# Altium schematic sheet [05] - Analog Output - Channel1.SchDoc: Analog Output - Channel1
size A2; DrawnBy: Ankur Dubey; DocumentNumber: 5; SheetNumber: 5; SheetTotal: 16
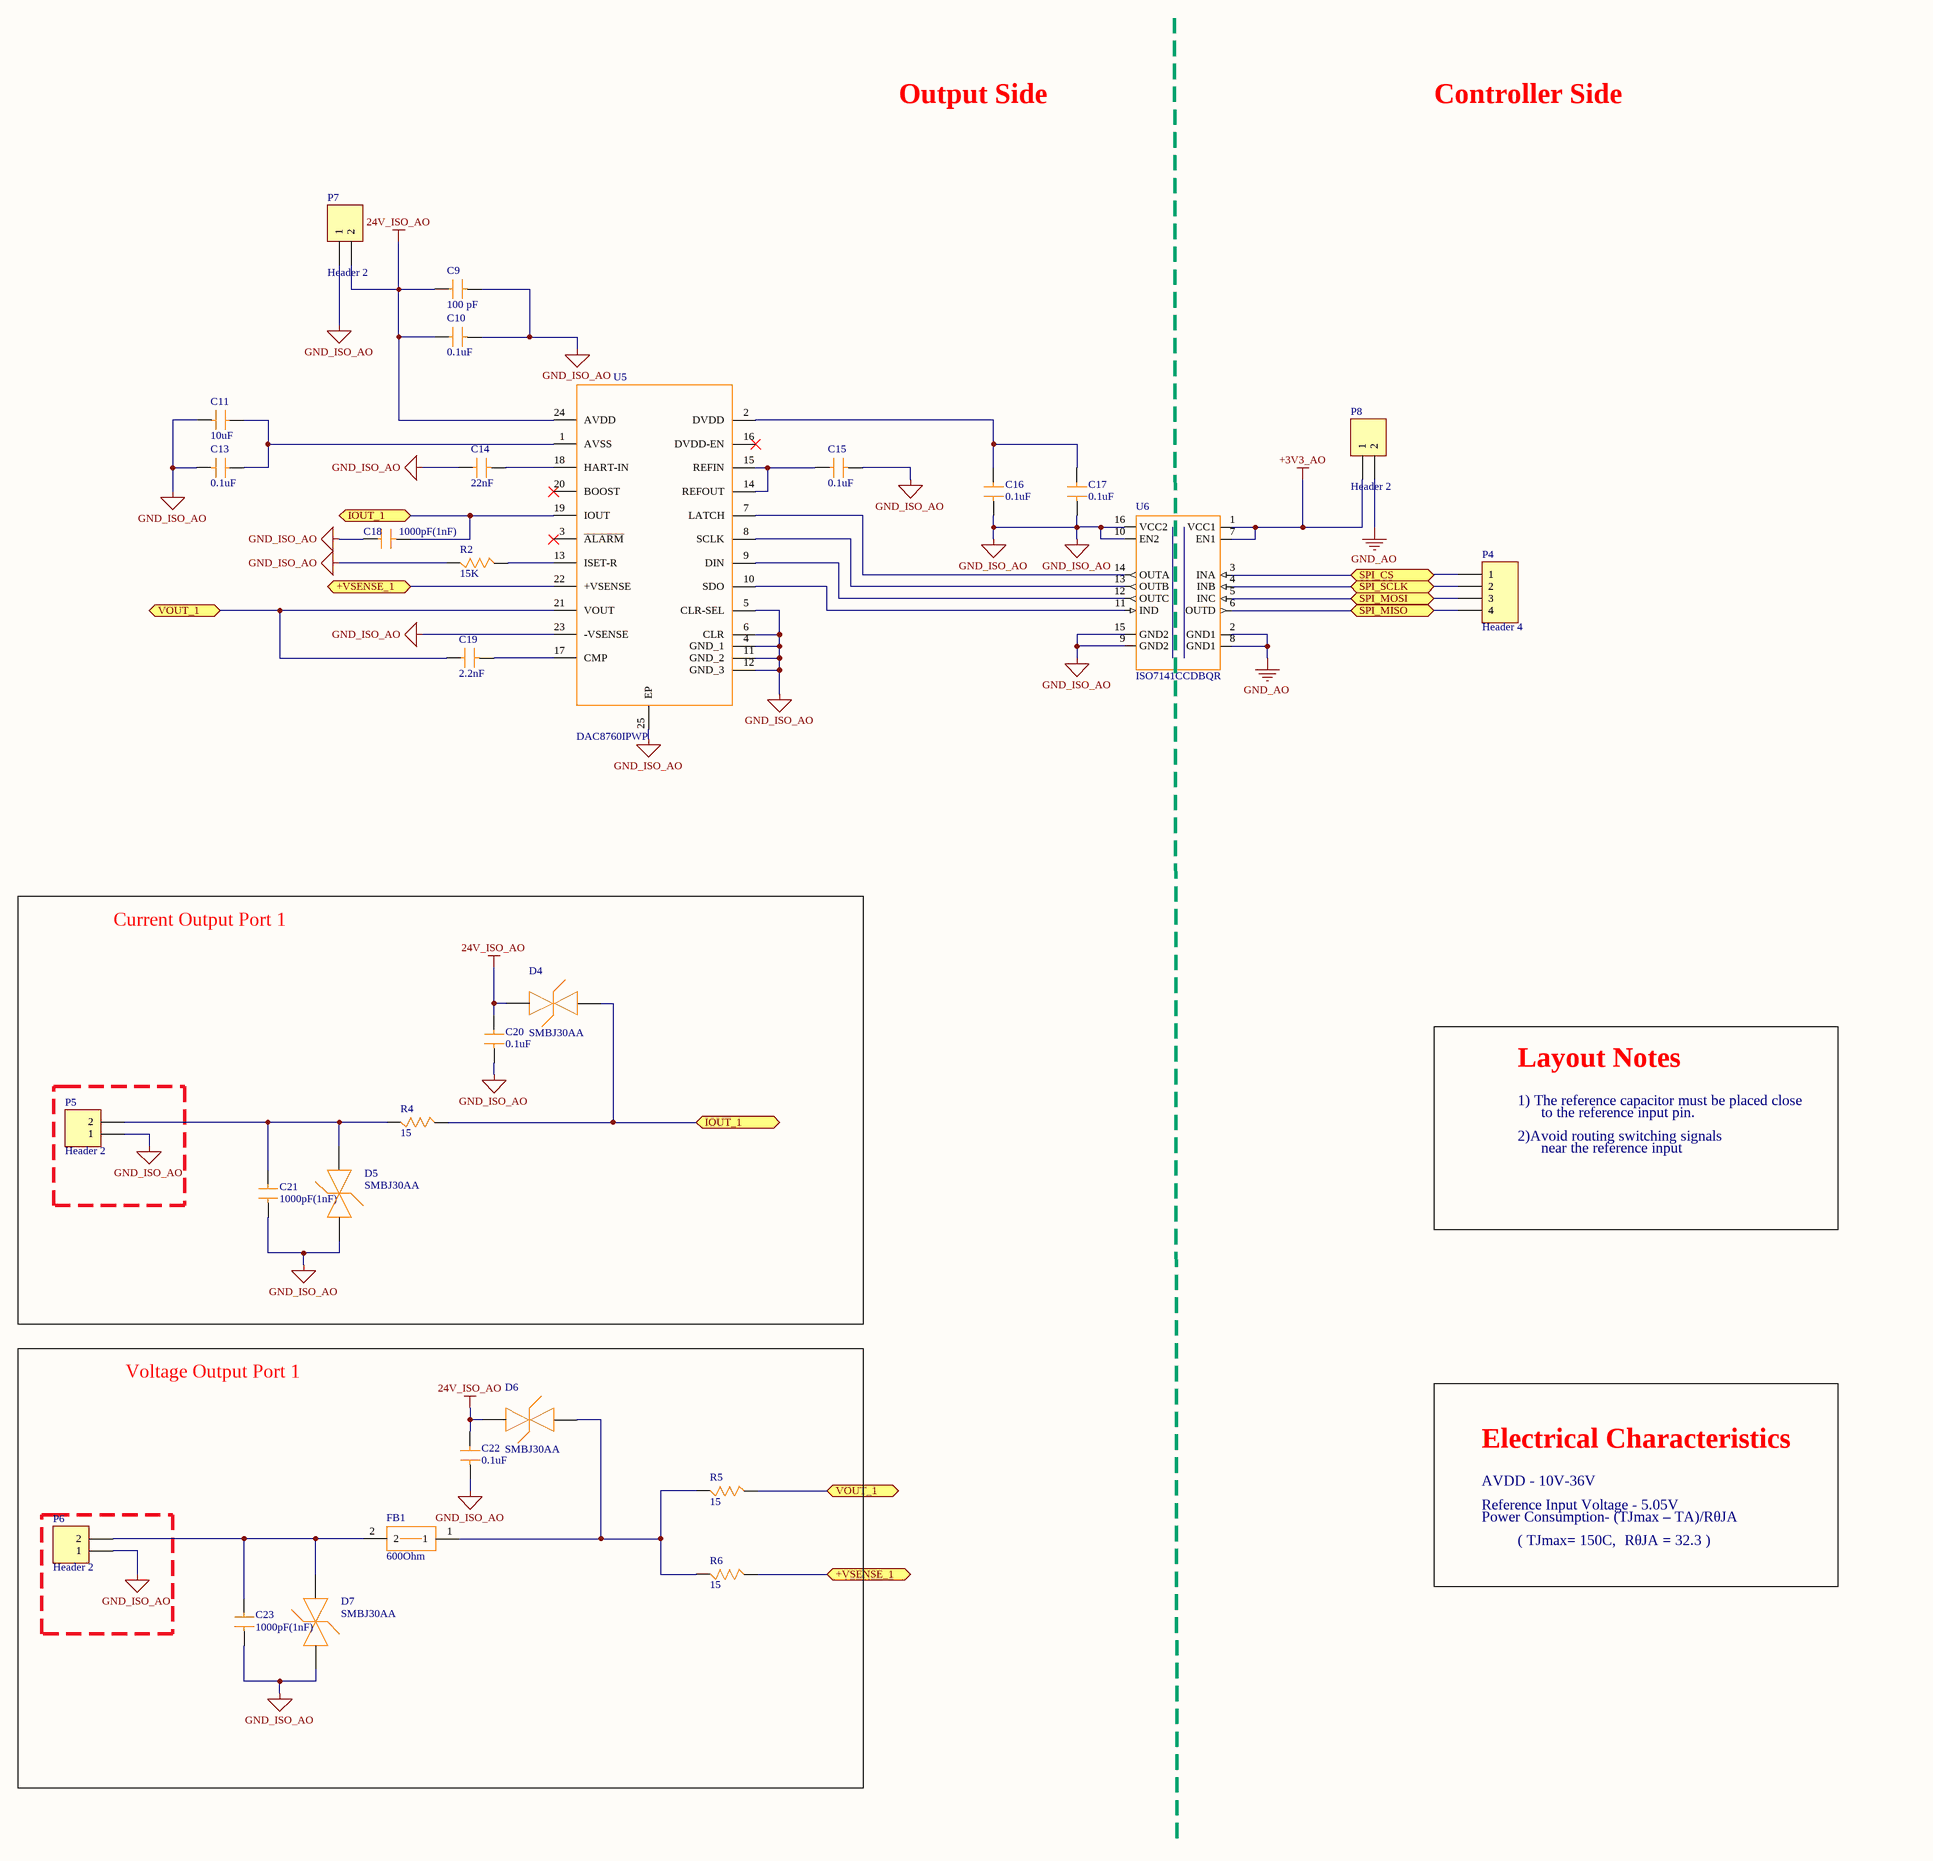
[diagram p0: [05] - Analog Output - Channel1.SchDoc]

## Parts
C9  100 pF  [C0805]
C10  0.1uF  [C0805]
C11  10uF  [C0805]
C13  0.1uF  [C0805]
C14  22nF  [C0805]
C15  0.1uF  [C0805]
C16  0.1uF  [C0805]
C17  0.1uF  [C0805]
C18  1000pF(1nF)  [C0805]
C19  2.2nF  [C0805]
C20  0.1uF  [C0805]
C21  1000pF(1nF)  [C0805]
C22  0.1uF  [C0805]
C23  1000pF(1nF)  [C0805]
D4  SMBJ30AA  [SMBJ30-AA]
D5  SMBJ30AA  [SMBJ30-AA]
D6  SMBJ30AA  [SMBJ30-AA]
D7  SMBJ30AA  [SMBJ30-AA]
FB1  600Ohm  [FB_0805]
P4  Header 4  [HDR1X4]
P5  Header 2  [HDR1X2]
P6  Header 2  [HDR1X2]
P7  Header 2  [HDR1X2]
P8  Header 2  [HDR1X2]
R2  15K  [R0805]
R4  15  [R0805]
R5  15  [R0805]
R6  15  [R0805]
U5  DAC8760IPWP  [DAC8760IPWP]
U6  ISO7141CCDBQR  [ISO7141CCDBQR]

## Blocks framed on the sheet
Current Output Port 1: C20 C21 D4 D5 P5 R4
Voltage Output Port 1: C22 C23 D6 D7 FB1 P6 R5 R6

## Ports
+VSENSE_1, IOUT_1, SPI_CS, SPI_MISO, SPI_MOSI, SPI_SCLK, VOUT_1

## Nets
24V_ISO_AO: C9.2 C10.2 C20.2 C22.2 D4.2(A) D6.2(A) P7.2 U5.24(AVDD)
+3V3_AO: P8.1 U6.1(VCC1) U6.7(EN1)
GND_AO: P8.2 U6.2(GND1) U6.8(GND1)
GND_ISO_AO: C9.1 C10.1 C11.1 C13.1 C14.2 C15.1 C16.1 C17.1 C18.2 C20.1 C21.1 C22.1 C23.1 D5.2(A) D7.2(A) P5.1 P6.1 P7.1 R2.2 U5.4(GND_1) U5.5(CLR-SEL) U5.6(CLR) U5.11(GND_2) U5.12(GND_3) U5.23(-VSENSE) U5.25(EP) U6.9(GND2) U6.10(EN2) U6.15(GND2) U6.16(VCC2)
+VSENSE_1: R6.1 U5.22(+VSENSE) ; port +VSENSE_1
IOUT_1: C18.1 D4.1(K) R4.1 U5.19(IOUT) ; port IOUT_1
SPI_CS: P4.1 U6.3(INA) ; port SPI_CS
SPI_MISO: P4.4 U6.6(OUTD) ; port SPI_MISO
SPI_MOSI: P4.3 U6.5(INC) ; port SPI_MOSI
SPI_SCLK: P4.2 U6.4(INB) ; port SPI_SCLK
VOUT_1: C19.2 R5.1 U5.21(VOUT) ; port VOUT_1
NetC11_2: C11.2 C13.2 U5.1(AVSS)
NetC14_1: C14.1 U5.18(HART-IN)
NetC15_2: C15.2 U5.14(REFOUT) U5.15(REFIN)
NetC16_2: C16.2 C17.2 U5.2(DVDD)
NetC19_1: C19.1 U5.17(CMP)
NetC21_2: C21.2 D5.1(K) P5.2 R4.2
NetC23_2: C23.2 D7.1(K) FB1.2 P6.2
NetD6_1: D6.1(K) FB1.1 R5.2 R6.2
NetR2_1: R2.1 U5.13(ISET-R)
NetU5_7: U5.7(LATCH) U6.14(OUTA)
NetU5_8: U5.8(SCLK) U6.13(OUTB)
NetU5_9: U5.9(DIN) U6.12(OUTC)
NetU5_10: U5.10(SDO) U6.11(IND)

Not connected (* = marked no-connect by the designer): U5 3(~{ALARM})* 16(DVDD-EN)* 20(BOOST)*

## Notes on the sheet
- Output Side
- Controller Side
- Layout Notes
- 1) The reference capacitor must be placed close
- 2)Avoid routing switching signals
- to the reference input pin.
- near the reference input
- Electrical Characteristics
- AVDD - 10V-36V
- Reference Input Voltage - 5.05V
- Power Consumption- (TJmax – TA)/RθJA
- ( TJmax= 150C,
- RθJA = 32.3 )

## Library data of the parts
C9 = C_0805-1nF-50V: Multilayer Ceramic Capacitors MLCC - SMD/SMT 50V 1000pF X7R 0805 10% AEC-Q200; Manufacturer: KEMET; Manufacturer Part Number: C0805J102K5RACAUTO; Type: X7R Dielectric; Voltage Rating DC: 50 VDC; Capacitance - nF: 1 nF; Capacitance - uF: 0.001 uF; Class: Class 2; Product Status: New Product
C10 C13 C15-C17 C20 C22 = C_0805-0.1uF: Multilayer Ceramic Capacitors MLCC - SMD/SMT 0.1uF 10% 50V AEC-Q200; Manufacturer: Yageo; Manufacturer Part Number: AS0805KKX7R9BB104; Voltage Rating DC: 50 VDC; Capacitance - nF: 100 nF; Capacitance - pF: 100000 pF; CNHTS: 8532241000; Dielectric: X7R; TARIC: 8532240000; Product Status: New Product
C11 = C_0805-10uF: Multilayer Ceramic Capacitors MLCC - SMD/SMT 10uF 10% 25V; Manufacturer: Yageo; Manufacturer Part Number: CC0805KFX5R8BB106; Type: MLCC Surface Mount Ceramic Capacitor; Voltage Rating DC: 25 VDC; Class: Class 2; CNHTS: 8532241000; Dielectric: X5R; TARIC: 8532240000; Product Status: New Product
C14 C19 = C_0805-22uF: Multilayer Ceramic Capacitors MLCC - SMD/SMT 22uF 20% 6.3V; Manufacturer: Yageo; Manufacturer Part Number: CC0805MFX5R5BB226; Type: MLCC Surface Mount Ceramic Capacitor; Voltage Rating DC: 6.3 VDC; Class: Class 2; CNHTS: 8532241000; Dielectric: X5R; TARIC: 8532240000
C18 C21 C23 = C_0805-1000pF(1nF): Multilayer Ceramic Capacitors MLCC - SMD/SMT 200V 1000pF X7R 0805 10% AEC-Q200; Manufacturer: KEMET; Manufacturer Part Number: C0805C102K2RECAUTO; Voltage Rating DC: 200 VDC; Capacitance - uF: 0.001 uF; Class: Class 2; CNHTS: 8532241000; TARIC: 8532240000; Product Status: New Product
D4-D7 = SMBJ30-AA: ESD Suppressors / TVS Diodes 30V 600W UNI 10%; Manufacturer: Crydom; Manufacturer Part Number: SMBJ30; Breakdown Voltage: 33.3 V; Clamping Voltage: 53.5 V; Polarity: Unidirectional; Product Status: Obsolete
FB1 = FB_0805-220, 3000mA: Ferrite Beads NEW MFG PN 810-MPZ2012S221AT000; Manufacturer: TDK; Impedance: 220 Ohms; Maximum DC Current: 3 A; Maximum DC Resistance: 40 mOhms; Tolerance: 25 %; Type: Chip Bead SMD for Power Line; Test Frequency: 100 MHz; Product Status: Part Number Change
P4 = Header 4: Header, 4-Pin
P5-P8 = Header 2: Header, 2-Pin
R2 R4-R6 = R_0805-15: Thin Film Resistors - SMD 15 Ohms 0.1% Tol. AEC-Q200; Manufacturer: Yageo; Manufacturer Part Number: AT0805BRD0715RL; Power Rating: 125 mW (1/8 W); Resistance: 15 Ohms; Temperature Coefficient: 25 PPM / C; Voltage Rating: 150 V; CNHTS: 8533211000; MXHTS: 85332101; TARIC: 8533210000
U5 = DAC8760IPWP: Digital to Analog Converters - DAC 1-CH 16B Prgrmmble Crnt/VTG Out DAC; Manufacturer: Texas Instruments; Number of Converters: 1 Converter; Output Type: Current, Voltage; Power Consumption: 135 mW; Resolution: 16 bit; Interface Type: Serial, SPI; Number of Channels: 1 Channel; Reference Type: External, Internal; Analog Supply Voltage: 10 V to 36 V; Development Kit: DAC8760EVM; Digital Supply Voltage: 2.7 V to 5.5 V; DNL - Differential Nonlinearity: +/- 1 LSB; Gain Error: 0.07 % FSR; Pd - Power Dissipation: 170 mW; Settling Time: 25 us; Supply Voltage - Max: 5.5 V; Supply Voltage - Min: 2.7 V
U6 = ISO7141CCDBQR: Digital Isolators Small-FP & Low-Pwr 3/1 Quad Ch Dig Iso; Manufacturer: Texas Instruments; Data Rate: 50 Mb/s; Input Type: CMOS, TTL; Isolation Voltage: 2.5 kVrms; Output Type: CMOS; Number of Channels: 4 Channel; Shutdown: No Shutdown; Forward Channels: 3 Channel; Isolation Type: Capacitive Coupling; Operating Supply Current: 14 mA; Operating Supply Voltage: 2.7 V to 5 V; Pd - Power Dissipation: 150 mW; Propagation Delay Time: 23 ns; Reverse Channels: 1 Channel; Supply Voltage - Max: 5 V; Supply Voltage - Min: 2.7 V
